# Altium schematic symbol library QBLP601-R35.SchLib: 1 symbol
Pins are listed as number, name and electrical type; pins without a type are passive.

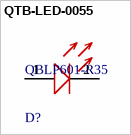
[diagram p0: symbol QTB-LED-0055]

## QTB-LED-0055
designator D?, comment QBLP601-R35
LED RED CLEAR 0603 SMD; Manufacturer: QT Brightek (QTB); Lens Size: 0.8mm; Luminous Intensity: 27mcd; Test Current: 5mA; Lens Color: Colorless; Lens Style: Flat; Forward Voltage: 1.9V; Wavelength - Dominant: 631nm
footprint QBLP601-R35-MFG
pins: 1 ANODE (+), 2 CATHODE (-)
